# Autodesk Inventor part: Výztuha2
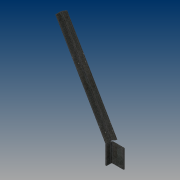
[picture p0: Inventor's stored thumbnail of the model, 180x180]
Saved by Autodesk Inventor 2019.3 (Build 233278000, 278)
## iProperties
Created: 2019-02
Part Number: Výztuha2
Material: Ocel, měkká, svařovaná
Document SubType Name: Plech
Designer: B-hon
Density: 7.85 g/cm^3
Sheet Metal Rule: Výchozí_mm
Appearance: Plech
Author: B-hon
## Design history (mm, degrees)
node "Plocha1"
  sketch "Náčrt1"
    geometry: L1 (-7, 0)-(-48, 0); L2 (-48, 0)-(-48, 390); L3 (-7, 390)-(-7, 0); L4 (-48, 390)-(-7, 390); 5 further points
    constraints: 8 end point, 2 horizontal alignment, 1 horizontal, 1 parallel, 1 perpendicular
    dimensions: "d5" = 7 vertical distance of point (0, 0) point (-17, 7); "d6" = 17 horizontal distance of point (0, 0) point (-17, 7); "d7" = 21 distance of point (-38, 7) point (-17, 7); "d8" = 45 vertical distance of point (-17, 7) point (-27.5, 52); "d9" = 10.5 horizontal distance of point (-17, 7) point (-27.5, 52) (= 0.5 x d7); "d10" = 10 distance from line of point (-17, 7) L3; "d11" = 10 distance from line of point (-38, 7) L2 (= d10); "d12" = 250 distance from line of L3 point (243, 370); "d13" = 370 distance from line of L1 point (243, 370); "d15" = 390 distance of L1.end L2.end
node "Obruba4"
sketch "Náčrt9"
  geometry: L1 (14, 0)-(14, 390) reference; L2 (29.659, 62)-(14, 62); L3 (14, 62)-(14, 60); L4 (14, 60)-(29.659, 60); L5 (29.659, 60)-(29.659, 62); L6 (17, 0)-(14, 0) reference; 1 further point
  constraints: 8 end point, 2 parallel, 1 horizontal, 1 perpendicular, 1 point on line
  dimensions: "d83" = 2 distance of L4.end L2.start; "d84" = 60 distance between parallel lines of L6 L4
extrude "Vysunutí2" cut sketch "Náčrt9" stored distance "d85" = 200; taper "d86" = 0 deg
sketch "Náčrt10"
  geometry: L1 (-67.25, 60)-(25.208, 60); L2 (-20, 60)-(-14, 60) reference; 1 further point
  constraints: 2 end point, 1 collinear
  dimensions: "d87" = 0 distance between parallel lines of L1 L2
feature "Ohyb součásti2" sketch "Náčrt10" dims "d88" = 3, "d89" = 30 deg
node "Upravit přímo2"
sketch "Náčrt11"
  geometry: L1 (48, 60)-(48, 0) reference; L2 (7, 0)-(42, 0) reference; 4 further points
  constraints: 1 horizontal alignment
  dimensions: "d93" = 14 distance from line of point (34, 7) L1; "d94" = 7 distance from line of L2 point (34, 7); "d95" = 21 distance of point (34, 7) point (13, 7); "d96" = 45 vertical distance of point (34, 7) point (23.5, 52); "d97" = 10.5 horizontal distance of point (34, 7) point (23.5, 52) (= 0.5 x d95)
hole "Díra2" sketch "Náčrt11" at (34, 7), (13, 7), (23.5, 52) diameter "d98" = 5.5; stored, may be unused: countersink angle "d102" = 90 deg, drill point angle "d104" = 0 deg; dims "d99" = 6, "d100" = 4, "d101" = 2, "d103" = 3 (= Tloušťka)
node "Upravit přímo3"
node "Těleso1"
feature "Deska1" dims "d14" = 3 (= Tloušťka)
sketch "Náčrt8"
  geometry: L1 through (-195, 0) direction (1, 1.12e-48); L2 through (0, 10) direction (1.23e-32, 1); L3 (0, 20)-(-390, 20); L4 (-390, 20)-(-390, 0)
  constraints: 6 end point, 1 horizontal, 1 perpendicular, 1 vertical
feature "Deska5" dims "d14" = 3 (= Tloušťka), "d73" = 3 (= ŠířkaVýštipu), "d74" = 1.5 (= HloubkaVýštipu), "d75" = 6 (= MinimálníZbytek), "d76" = 3 (= PřechodovýPoloměr), "d77" = 20, "d78" = 90 deg, "d79" = 3 (= PoloměrOhybu), "d80" = 12 (= VelikostRohovéhoVýštipu), "d81" = 3 (= VelikostMezery), "d82" = 3 (= VelikostJacobihoPoloměru), "MezeraVystřižení" = 0.01
feature "Ohyb4" dims "d14" = 3 (= Tloušťka), "d73" = 3 (= ŠířkaVýštipu), "d74" = 1.5 (= HloubkaVýštipu), "d75" = 6 (= MinimálníZbytek), "d76" = 3 (= PřechodovýPoloměr), "d77" = 20, "d78" = 90 deg, "d79" = 3 (= PoloměrOhybu), "MezeraVystřižení" = 0.01
feature "Roh4" dims "d77" = 20, "d78" = 90 deg, "d80" = 12 (= VelikostRohovéhoVýštipu), "d81" = 3 (= VelikostMezery), "d82" = 3 (= VelikostJacobihoPoloměru)
feature "Posunout2" dims "d92" = -20
feature "Posunout3" dims "d107" = 1
other parameters: "Tloušťka" = 3 (derived), "KSoučinitel" = 4.4, "PoloměrOhybu" = 3 (= Tloušťka), "ŠířkaVýštipu" = 3 (= Tloušťka), "HloubkaVýštipu" = 1.5 (= 0.5 x Tloušťka), "VelikostRohovéhoVýštipu" = 12 (= 4 x Tloušťka), "MinimálníZbytek" = 6 (= 2 x Tloušťka), "PřechodovýPoloměr" = 3 (= PoloměrOhybu), "VelikostJacobihoPoloměru" = 3 (= PoloměrOhybu), "VelikostMezery" = 3 (= Tloušťka), "d90" = 0, "d91" = 0, "d105" = 0, "d106" = 0
